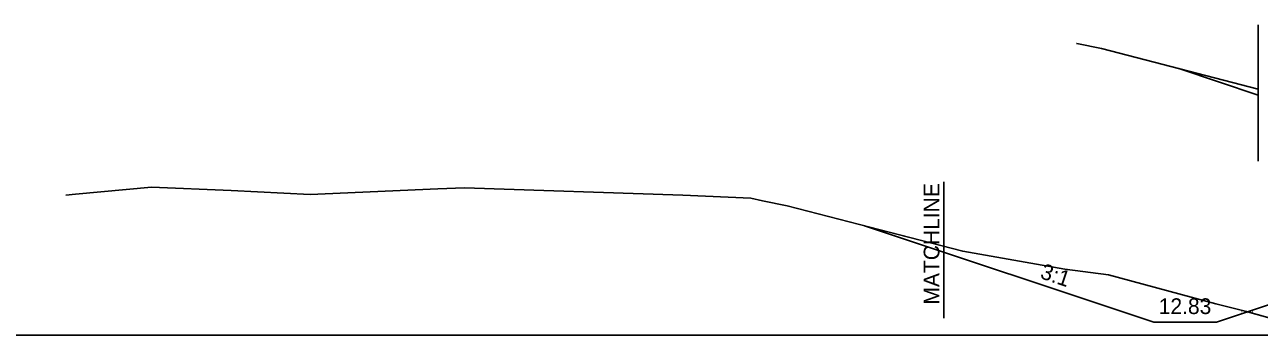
# Model space of a CAD drawing. Extents: x 2207892 to 2209721, y 61220 to 65449.
# Drawn here: x 2207984.7 to 2208063.3, y 64407.3 to 64427.1 of the extents above; entities that cross this region are included whole.
import ezdxf

# ---------------------------------------------------------------- set-up
doc = ezdxf.new("R2010")
doc.units = 0
for name, color, linetype in [('Exist DTM Breakline Cogo Comment', 7, 'Continuous'), ('Exist DTM Breakline Cogo Elevation', 7, 'Continuous'), ('Exist DTM Breakline Underwater Cogo Comment', 7, 'Continuous'), ('Exist Hydro Stream or Body of Water Cogo Elevation', 7, 'Continuous'), ('Exist Roads EOP Other Cogo Elevation', 7, 'Continuous'), ('Exist Roads EOP Other Cogo Number', 7, 'Continuous'), ('Exist Structure Minor Head and End Wall Cogo Point CELL', 7, 'Continuous')]:
    doc.layers.add(name, color=color, linetype=linetype)

msp = doc.modelspace()

# ---------------------------------------------------------------- linework, layer by layer
at = {"layer": 'Exist DTM Breakline Cogo Comment'}
for points in [[(2208064.863, 64408.136), (2208080.823, 64413.744), (2208081.546, 64413.99), (2208082.147, 64414.133), (2208090.865, 64416.412), (2208096.235, 64417.116), (2208098.977, 64417.457), (2208099.385, 64417.617), (2208094.327, 64417.314), (2208093.43, 64418.211), (2208089.891, 64417.928), (2208062.5, 64408.797)], [(2208060.483, 64409.32), (2208062.438, 64408.815), (2208062.5, 64408.797), (2208060.529, 64408.14), (2208056.529, 64408.14), (2208038.118, 64414.277), (2208044.373, 64412.661), (2208050.878, 64411.525), (2208053.66, 64411.163)]]:
    msp.add_lwpolyline(points, close=True, dxfattribs=at)
at = {"layer": 'Exist DTM Breakline Cogo Elevation'}
for p, q in [((2208063.174, 64418.397), (2208063.174, 64427.069)), ((2208063.174, 64422.592), (2208058.118, 64424.277)), ((2208043.174, 64408.397), (2208043.174, 64417.069))]:
    msp.add_line(p, q, dxfattribs=at)
msp.add_lwpolyline([(2208051.614, 64425.873), (2208051.636, 64425.868), (2208053.197, 64425.549), (2208063.174, 64422.971)], dxfattribs=at)
at = {"layer": 'Exist Hydro Stream or Body of Water Cogo Elevation'}
for p, q in [((2208056.529, 64408.14), (2208038.118, 64414.277)), ((2208060.529, 64408.14), (2208056.529, 64408.14))]:
    msp.add_line(p, q, dxfattribs=at)
msp.add_lwpolyline([(2208095.891, 64418.408), (2208089.891, 64417.928), (2208060.529, 64408.14)], dxfattribs=at)
at = {"layer": 'Exist Roads EOP Other Cogo Elevation'}
msp.add_lwpolyline([(2207987.3, 64416.224), (2207987.905, 64416.284), (2207992.738, 64416.74), (2207997.821, 64416.529), (2208002.853, 64416.259), (2208010.96, 64416.632), (2208012.672, 64416.696), (2208026.555, 64416.215), (2208030.881, 64416.03), (2208031.636, 64415.868), (2208033.197, 64415.549), (2208044.373, 64412.661), (2208050.878, 64411.525), (2208053.66, 64411.163), (2208060.483, 64409.32), (2208062.438, 64408.815), (2208064.863, 64408.136)], dxfattribs=at)
at = {"layer": 'Exist Roads EOP Other Cogo Number'}
msp.add_line((2207918.174, 64407.31), (2208118.174, 64407.31), dxfattribs=at)

# ---------------------------------------------------------------- texts
at = {"layer": 'Exist DTM Breakline Cogo Elevation'}
msp.add_text('MATCHLINE', height=1, rotation=90, dxfattribs=at).set_placement((2208042.89, 64409.265))
at = {"layer": 'Exist DTM Breakline Underwater Cogo Comment'}
msp.add_text('3:1', height=1, rotation=341.56505, dxfattribs=at).set_placement((2208049.244, 64410.957))
msp.add_text('12.83', height=1, dxfattribs=at).set_placement((2208056.85, 64408.662))
at = {"layer": 'Exist Structure Minor Head and End Wall Cogo Point CELL'}
msp.add_text('LT_Slope_Fill', height=0.1, dxfattribs=at).set_placement((2208062.024, 64408.748))

doc.saveas('drawing.dxf')
